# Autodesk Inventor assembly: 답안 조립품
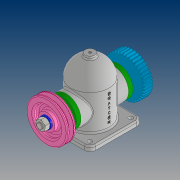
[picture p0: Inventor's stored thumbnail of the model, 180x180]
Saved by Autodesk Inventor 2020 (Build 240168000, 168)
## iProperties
Created: 2021-08
Part Number: 답안 조립품
Document SubType Name: Assembly
Designer: PC312-
Author: PC312-
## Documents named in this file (14)
- C:\Users\PC312-\Desktop\710809V1009\답안 조립품.iam
- C:\Users\PC312-\Desktop\710809V1009\본체.ipt
- C:\Users\PC312-\Desktop\710809V1009\V-벨트풀리.ipt
- V-벨트풀리.ipt
- C:\Users\PC312-\Desktop\710809V1009\너트 M12x1.25.ipt
- C:\Users\PC312-\Desktop\710809V1009\베어링 6203.ipt
- C:\Users\PC312-\Desktop\710809V1009\볼트 M4.ipt
- C:\Users\PC312-\Desktop\710809V1009\부시.ipt
- C:\Users\PC312-\Desktop\710809V1009\스퍼기어.ipt
- C:\Users\PC312-\Desktop\710809V1009\오일 실 26 38 8.ipt
- C:\Users\PC312-\Desktop\710809V1009\와셔 12x24.ipt
- C:\Users\PC312-\Desktop\710809V1009\축.ipt
- C:\Users\PC312-\Desktop\710809V1009\커버.ipt
- C:\Users\PC312-\Desktop\710809V1009\키 5x5x12.ipt
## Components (1 placed, 1 different names)
1. V-벨트풀리:1
